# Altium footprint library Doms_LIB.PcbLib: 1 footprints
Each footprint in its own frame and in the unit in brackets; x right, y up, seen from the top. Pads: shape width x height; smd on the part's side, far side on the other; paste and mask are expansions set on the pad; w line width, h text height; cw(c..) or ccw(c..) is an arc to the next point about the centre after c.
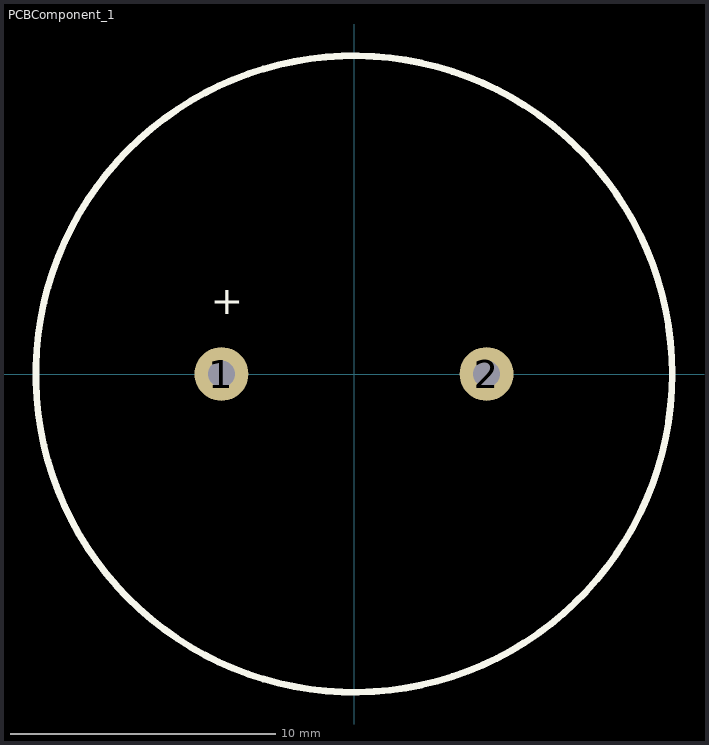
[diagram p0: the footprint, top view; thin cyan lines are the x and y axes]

## PCBComponent_1 [mil]
pads (2):
  round 80 hole 40: 1(-196.85,0) 2(196.85,0)
Top Overlay:
  circle w10: c0,0 r472.44
  text "+" at -212.6,74.8 h72.83
Bottom Overlay:
  text "-" at 173.23,86.61 h72.83
3D body: height 287.4, standoff 0, extent -472.42,-472.42 472.42,472.42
